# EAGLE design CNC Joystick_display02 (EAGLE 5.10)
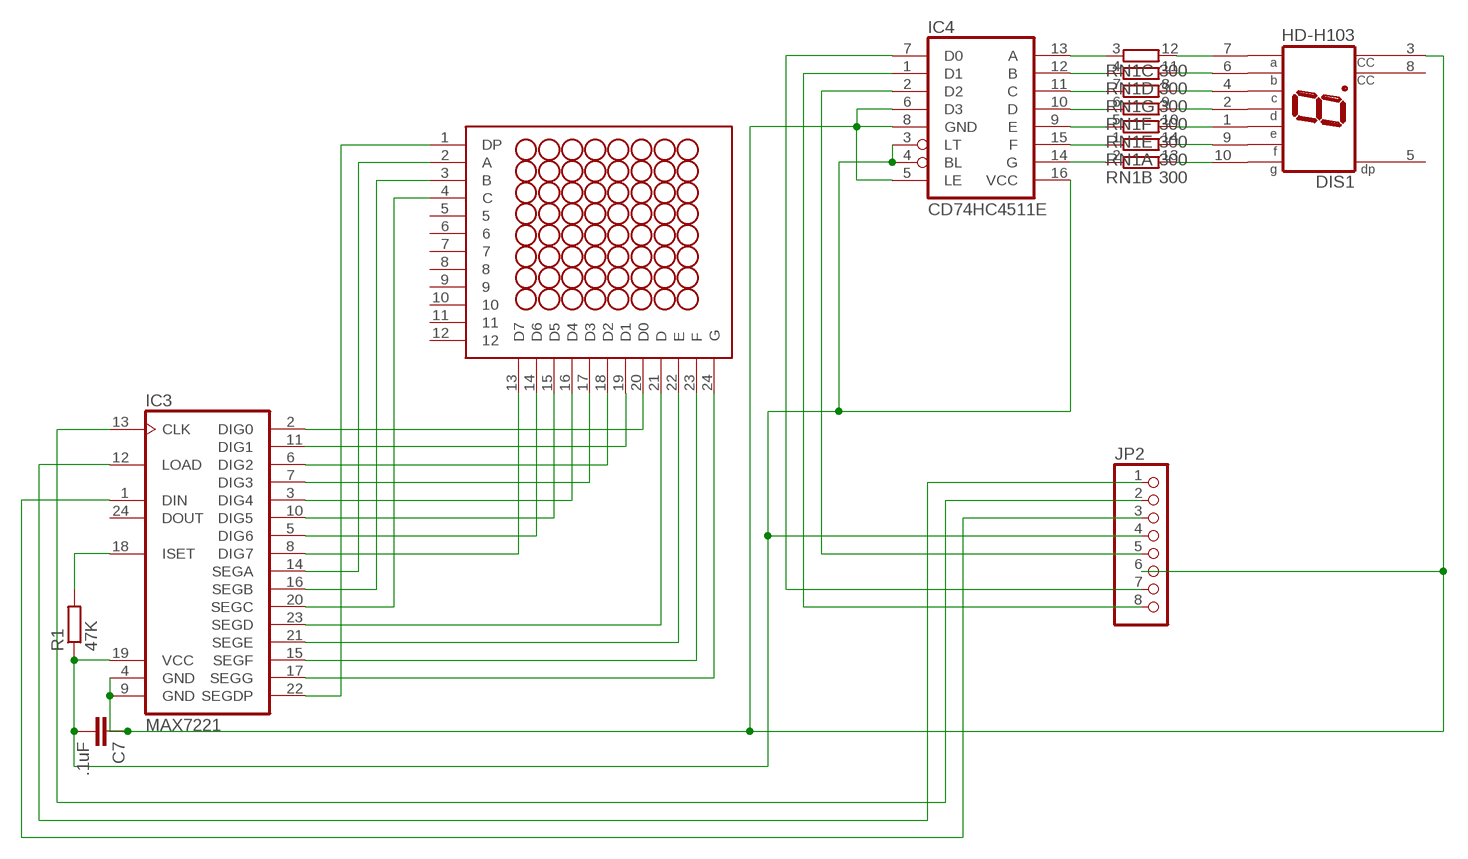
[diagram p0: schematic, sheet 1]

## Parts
C7  .1uF  C-EU050-024X044  [C050-024X044]
DIS1  HD-H103  [HDSP-M]
IC3  MAX7221  MAX7219CNG  [DIL24-3]
IC4  CD74HC4511E  4511N  [DIL16]
JP2  PINHD-1X8/90  [1X08/90]
R1  47K  R-EU_0207/10  [0207/10]
RN1  300  7R-N  [DIL14]
U$1  NFM-12881BG-11  [NFM-12881BG-11]

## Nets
N$1: IC4.13(A) RN1.3
N$2: IC4.12(B) RN1.4
N$3: IC4.9(E) RN1.5
N$4: IC4.10(D) RN1.6
N$5: DIS1.1(E) RN1.10
N$6: IC4.15(F) RN1.1
N$7: IC4.14(G) RN1.2
N$8: DIS1.7(A) RN1.12
N$9: DIS1.6(B) RN1.11
N$10: DIS1.4(C) RN1.8
N$11: DIS1.2(D) RN1.9
N$12: IC4.11(C) RN1.7
N$13: DIS1.9(F) RN1.14
N$14: DIS1.10(G) RN1.13
N$15: IC3.2(DIG0) U$1.20(D0)
N$16: IC3.11(DIG1) U$1.19(D1)
N$17: IC3.6(DIG2) U$1.18(D2)
N$18: IC3.7(DIG3) U$1.17(D3)
N$19: IC3.3(DIG4) U$1.16(D4)
N$20: IC3.10(DIG5) U$1.15(D5)
N$21: IC3.5(DIG6) U$1.14(D6)
N$22: IC3.8(DIG7) U$1.13(D7)
N$23: IC3.23(SEGD) U$1.21(D)
N$24: IC3.21(SEGE) U$1.22(E)
N$25: IC3.15(SEGF) U$1.23(F)
N$26: IC3.17(SEGG) U$1.24(G)
N$27: IC3.14(SEGA) U$1.2(A)
N$28: IC3.16(SEGB) U$1.3(B)
N$29: IC3.20(SEGC) U$1.4(C)
N$30: IC3.22(SEGDP) U$1.1(DP)
N$31: IC4.7(D0) JP2.7
N$33: IC3.13(CLK) JP2.2
N$34: IC4.2(D2) JP2.5
N$38: C7.1 DIS1.3(CC) IC3.4(GND) IC3.9(GND) IC4.5(LE) IC4.6(D3) IC4.8(GND) JP2.6
N$39: IC3.12(LOAD) JP2.1
N$40: IC3.18(ISET) R1.2
N$41: IC4.1(D1) JP2.8
N$44: IC3.1(DIN) JP2.3
N$55: C7.2 IC3.19(VCC) IC4.3(LT) IC4.4(BL) IC4.16(VCC) JP2.4 R1.1
Unconnected: DIS1.5(DP) DIS1.8(CC) IC3.24(DOUT) U$1.5 U$1.6 U$1.7 U$1.8 U$1.9 U$1.10 U$1.11 U$1.12

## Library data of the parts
C7 = rcl:C-EU: CAPACITOR, European symbol
DIS1 = display-hp:HD-H103: LED DISPLAY 1-character 7 segment, decimal point right
IC3 = maxim:MAX7219CNG: LED DISPLAY DRIVER
IC4 = CD74HC4511_BCD:4511: BCD to 7-segment LATCH/DECODER/DRIVER
JP2 = pinhead:PINHD-1X8: PIN HEADER
R1 = rcl:R-EU_: RESISTOR, European symbol
RN1 = resistor-dil:7R-N: DIL RESISTOR
U$1 = edeco:NFM-12881BG-11: 8x8 Red LED Matrix CMX1588ASR

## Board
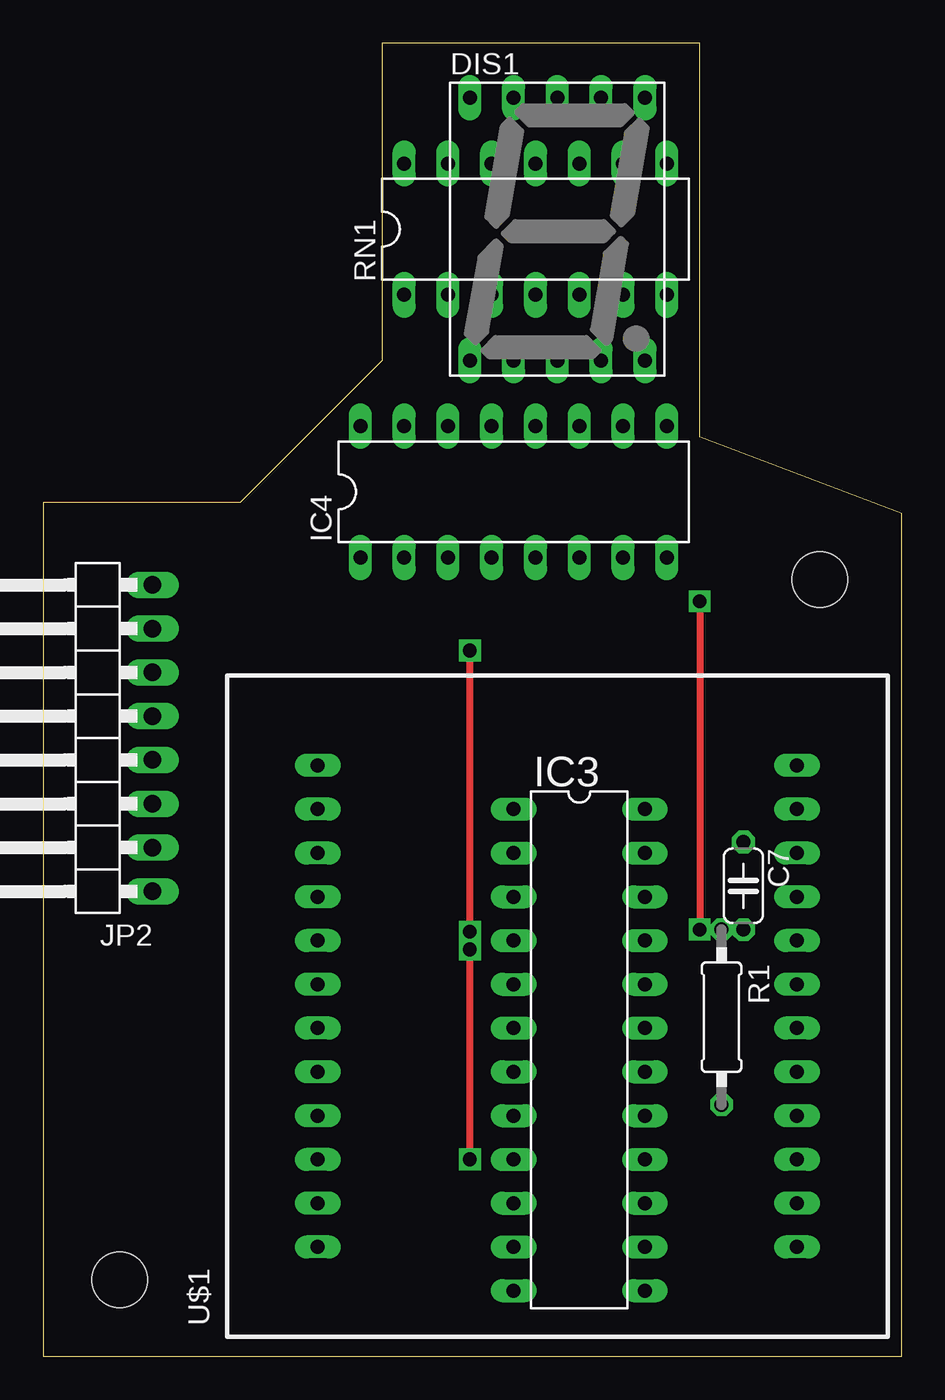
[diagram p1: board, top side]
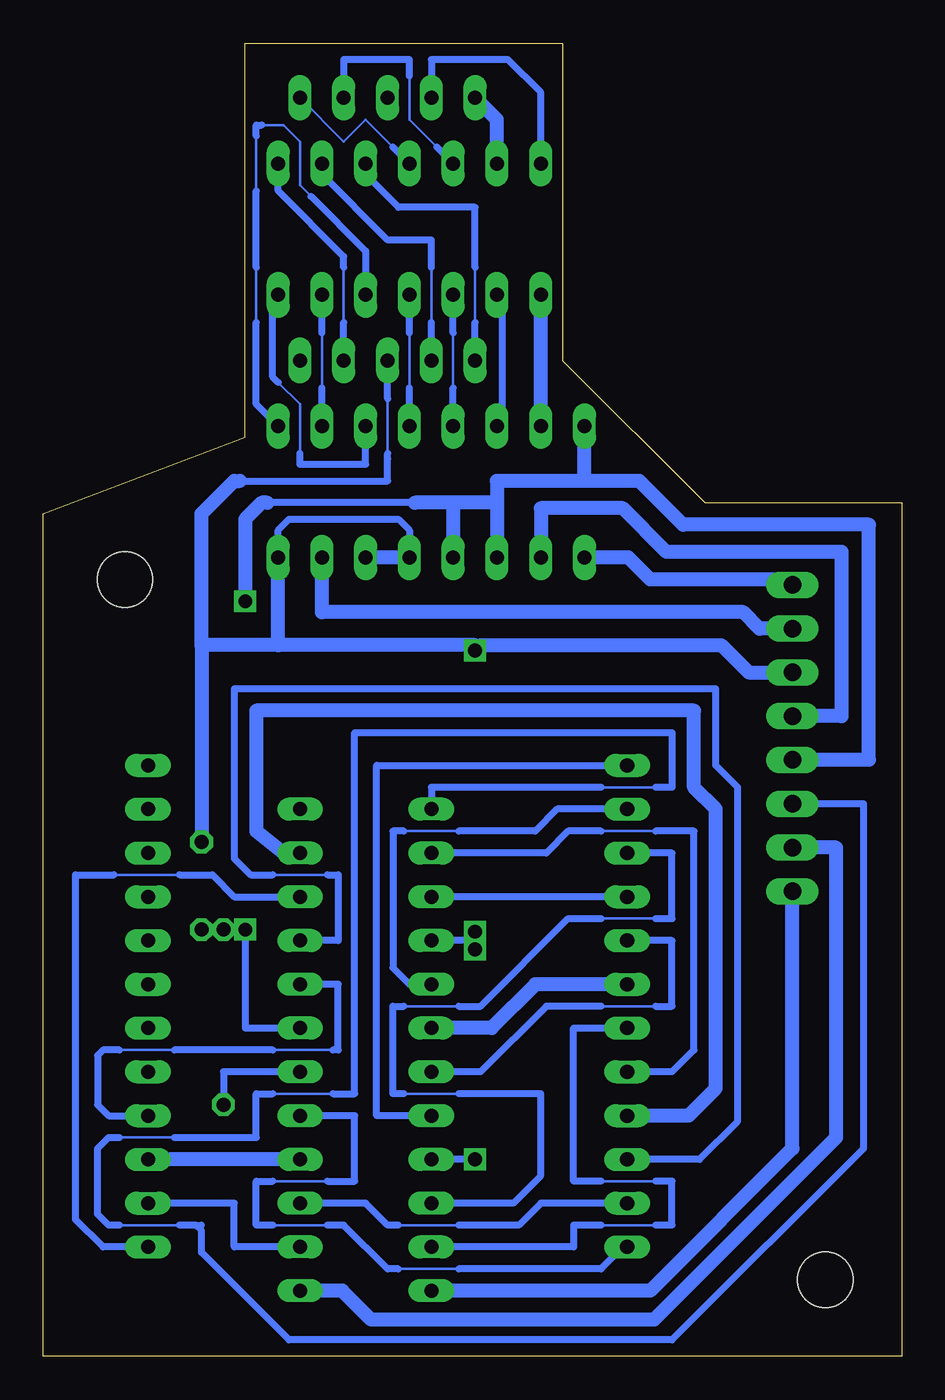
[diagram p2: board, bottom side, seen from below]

Size 49.84 x 76.2 mm. Coordinates in mm from the lower left corner, seen from the top.
Outline: 0,0 49.84,0 49.84,48.9 38.1,53.34 38.1,76.2 19.68,76.2 19.68,57.78 11.43,49.53 0,49.53 0,0
Copper layers (1*16): Top 0.035mm / dielectric 1.5mm / Bottom 0.035mm
Design rules "default": minimum track width 10mil, minimum drill 24mil, track to track 8mil, track to pad 8mil, pad to pad 8mil, via to via 8mil, smd to smd 8mil, copper to edge 40mil, drill to drill 8mil, minimum pad ring 10mil, minimum via ring 8mil, stop-mask expansion 4mil, vias tented up to drill 0mil, thermal gap 10mil
Holes 3.2 mm at 4.45,4.45 45.09,45.09
tRestrict: area 0.5,0.5 to 8.4,8.4; area 41.1,41.1 to 49.1,49.1

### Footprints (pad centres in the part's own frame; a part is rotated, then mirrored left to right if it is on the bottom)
C050-024X044 = drill 0.813 octagon: 1 -2.54,0; 2 2.54,0
HDSP-M = drill 0.813 long: 1 -5.08,-7.62; 2 -2.54,-7.62; 3 0,-7.62; 4 2.54,-7.62; 5 5.08,-7.62; 6 5.08,7.62; 7 2.54,7.62; 8 0,7.62; 9 -2.54,7.62; 10 -5.08,7.62
DIL24-3 = drill 0.813 long: 1 -13.97,-3.81; 2 -11.43,-3.81; 3 -8.89,-3.81; 4 -6.35,-3.81; 5 -3.81,-3.81; 6 -1.27,-3.81; 7 1.27,-3.81; 8 3.81,-3.81; 9 6.35,-3.81; 10 8.89,-3.81; 11 11.43,-3.81; 12 13.97,-3.81; 13 13.97,3.81; 14 11.43,3.81; 15 8.89,3.81; 16 6.35,3.81; 17 3.81,3.81; 18 1.27,3.81; 19 -1.27,3.81; 20 -3.81,3.81; 21 -6.35,3.81; 22 -8.89,3.81; 23 -11.43,3.81; 24 -13.97,3.81
DIL16 = drill 0.813 long: 1 -8.89,-3.81; 2 -6.35,-3.81; 3 -3.81,-3.81; 4 -1.27,-3.81; 5 1.27,-3.81; 6 3.81,-3.81; 7 6.35,-3.81; 8 8.89,-3.81; 9 8.89,3.81; 10 6.35,3.81; 11 3.81,3.81; 12 1.27,3.81; 13 -1.27,3.81; 14 -3.81,3.81; 15 -6.35,3.81; 16 -8.89,3.81
1X08/90 = drill 1.016 long: 1 -8.89,-3.81; 2 -6.35,-3.81; 3 -3.81,-3.81; 4 -1.27,-3.81; 5 1.27,-3.81; 6 3.81,-3.81; 7 6.35,-3.81; 8 8.89,-3.81
0207/10 = drill 0.813 octagon: 1 -5.08,0; 2 5.08,0
DIL14 = drill 0.813 long: 1 -7.62,-3.81; 2 -5.08,-3.81; 3 -2.54,-3.81; 4 0,-3.81; 5 2.54,-3.81; 6 5.08,-3.81; 7 7.62,-3.81; 8 7.62,3.81; 9 5.08,3.81; 10 2.54,3.81; 11 0,3.81; 12 -2.54,3.81; 13 -5.08,3.81; 14 -7.62,3.81
NFM-12881BG-11 = drill 0.813 long: 1 -13.97,-13.905; 2 -11.43,-13.905; 3 -8.89,-13.905; 4 -6.35,-13.905; 5 -3.81,-13.905; 6 -1.27,-13.905; 7 1.27,-13.905; 8 3.81,-13.905; 9 6.35,-13.905; 10 8.89,-13.905; 11 11.43,-13.905; 12 13.97,-13.905; 13 13.97,13.905; 14 11.43,13.905; 15 8.89,13.905; 16 6.35,13.905; 17 3.81,13.905; 18 1.27,13.905; 19 -1.27,13.905; 20 -3.81,13.905; 21 -6.35,13.905; 22 -8.89,13.905; 23 -11.43,13.905; 24 -13.97,13.905

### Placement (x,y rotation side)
C7  40.64,27.3 270 top
DIS1  29.84,65.41 0 top
IC3  31.11,17.78 270 top
IC4  27.3,50.16 0 top
JP2  2.54,35.88 90 top
R1  39.37,19.68 270 top
RN1  28.57,65.41 0 top
U$1  29.84,20.32 90 top

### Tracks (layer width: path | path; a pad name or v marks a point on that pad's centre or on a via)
N$1
  Bottom 0.152: 26.04,56.2 26.04,59.37
  Bottom 0.406: 26.04,59.37 RN1.3 | IC4.13 26.04,56.2
N$2
  Bottom 0.152: 28.57,56.2 28.57,59.37
  Bottom 0.406: 28.57,59.37 RN1.4 | IC4.12 28.57,56.2
N$3
  Bottom 0.152: 37.15,71.44 35.88,71.44 34.92,70.48 34.92,67.94 34.29,67.31 | 37.47,60.01 37.47,63.18 | 37.47,67.63 37.47,70.8
  Bottom 0.406: RN1.5 31.11,64.14 34.29,67.31 | IC4.9 37.47,55.24 37.47,60.01 | 37.15,71.44 37.47,71.44 37.47,70.8 | 37.47,63.18 37.47,67.63
N$4
  Bottom 0.152: 33.66,56.2 33.66,59.37
  Bottom 0.406: 33.66,59.37 RN1.6 | IC4.10 33.66,56.2
N$5
  Bottom 0.152: 24.77,60.01 24.77,63.18
  Bottom 0.406: RN1.10 31.11,68.58 29.21,66.67 24.77,66.67 24.77,63.18 | DIS1.1 24.77,60.01
N$6
  Bottom 0.813: IC4.15 RN1.1
N$7
  Bottom 0.406: IC4.14 23.18,53.98 23.18,61.59 RN1.2
N$8
  Bottom 0.152: 28.57,74.3 28.57,71.75 26.99,70.17
  Bottom 0.406: 28.57,74.3 28.57,75.25 32.38,75.25 DIS1.7 | RN1.12 26.99,70.17
N$9
  Bottom 0.152: DIS1.6 32.38,70.48 31.11,71.75 29.53,70.17
  Bottom 0.406: RN1.11 29.53,70.17
N$10
  Bottom 0.152: 32.38,60.01 32.38,63.18
  Bottom 0.406: DIS1.4 32.38,60.01 | 32.38,63.18 32.38,63.82 36.2,67.63 RN1.8
N$11
  Bottom 0.152: 27.3,60.01 27.3,63.18
  Bottom 0.406: RN1.9 33.66,68.58 29.84,64.77 27.3,64.77 27.3,63.18 | DIS1.2 27.3,60.01
N$12
  Bottom 0.152: 34.92,52.39 34.92,55.24 36.2,56.52
  Bottom 0.406: IC4.11 31.11,51.75 34.92,51.75 34.92,52.39 | RN1.7 36.51,61.28 36.51,56.83 36.2,56.52
N$13
  Bottom 0.406: RN1.14 20.95,73.34 22.86,75.25 27.3,75.25 DIS1.9
N$14
  Bottom 0.813: RN1.13 23.5,71.75 DIS1.10
N$15
  Bottom 0.152: 14.29,30.48 17.46,30.48
  Bottom 0.406: IC3.2 20.64,29.21 19.37,30.48 17.46,30.48 | 14.29,30.48 12.06,30.48 12.06,17.78 13.34,16.51 U$1.20
N$16
  Bottom 0.152: 14.29,7.62 17.46,7.62 | 14.29,10.16 17.46,10.16
  Bottom 0.406: IC3.11 19.05,6.35 19.05,7.62 17.46,7.62 | 17.46,10.16 19.05,10.16 19.05,19.05 U$1.19 | 14.29,7.62 13.34,7.62 13.34,10.16 14.29,10.16
N$17
  Bottom 0.813: IC3.6 23.81,19.05 21.27,21.59 U$1.18
N$18
  Bottom 0.152: 14.29,20.32 17.46,20.32
  Bottom 0.406: IC3.7 24.45,16.51 20.64,20.32 17.46,20.32 | 14.29,20.32 13.34,20.32 13.34,24.13 U$1.17
N$19
  Bottom 0.406: U$1.16 IC3.3
N$20
  Bottom 0.152: 17.46,25.4 14.29,25.4 | 28.89,20.32 25.72,20.32 | 25.72,15.24 28.89,15.24
  Bottom 0.406: IC3.10 22.54,8.89 20.95,10.48 20.95,15.24 25.72,15.24 | 14.29,25.4 13.34,25.4 13.34,29.21 U$1.15 | 17.46,25.4 19.37,25.4 24.45,20.32 25.72,20.32 | 28.89,20.32 29.53,20.32 29.53,15.24 28.89,15.24
N$21
  Bottom 0.152: 25.72,30.48 28.89,30.48
  Bottom 0.406: IC3.5 28.57,21.59 29.53,22.54 29.53,30.48 28.89,30.48 | 25.72,30.48 21.27,30.48 20,31.75 U$1.14
N$22
  Bottom 0.406: IC3.8 30.48,13.97 30.48,34.29 U$1.13
N$23
  Bottom 0.813: IC3.23 35.88,29.21 37.47,30.48 37.47,37.47 12.06,37.47 12.06,33.02 10.79,31.75 10.79,15.56 12.38,13.97 U$1.21
N$24
  Bottom 0.152: 36.51,27.94 33.34,27.94
  Bottom 0.406: 36.51,27.94 37.78,27.94 38.73,28.89 38.73,38.73 10.79,38.73 10.79,34.29 9.53,33.02 9.53,13.65 11.75,11.43 U$1.22 | IC3.21 32.7,24.13 32.7,27.94 33.34,27.94
N$25
  Bottom 0.152: 25.72,7.62 29.21,7.62
  Bottom 0.406: IC3.15 31.11,8.89 29.84,7.62 29.21,7.62 | 25.72,7.62 22.23,7.62 20.95,8.89 U$1.23
N$26
  Bottom 0.152: 25.72,5.08 29.21,5.08 | 36.51,10.16 33.34,10.16 | 33.34,7.62 36.51,7.62
  Bottom 0.406: IC3.17 31.75,13.97 31.75,10.16 33.34,10.16 | 33.34,7.62 32.38,7.62 29.84,5.08 29.21,5.08 | 25.72,5.08 17.46,5.08 16.19,6.35 U$1.24 | 36.51,10.16 37.47,10.16 37.47,7.62 36.51,7.62
N$27
  Bottom 0.406: IC3.14 38.73,6.35 38.73,8.89 U$1.2
N$28
  Bottom 0.813: IC3.16 U$1.3
N$29
  Bottom 0.152: 33.02,17.78 36.51,17.78 | 42.23,17.78 45.4,17.78
  Bottom 0.406: U$1.4 46.04,13.97 46.67,14.61 46.67,17.46 46.35,17.78 45.4,17.78 | IC3.20 32.7,21.59 32.7,17.78 33.02,17.78 | 36.51,17.78 42.23,17.78
N$30
  Bottom 0.152: 45.72,27.94 41.91,27.94
  Bottom 0.406: IC3.22 38.73,26.67 40.01,27.94 41.91,27.94 | 45.72,27.94 47.94,27.94 47.94,7.94 46.35,6.35 U$1.1
N$31
  Bottom 0.813: IC4.7 33.66,43.18 9.21,43.18 8.26,42.23 JP2.7
N$33
  Bottom 0.813: JP2.2 3.81,29.53 3.81,12.7 14.38,2.13 30.8,2.13 32.48,3.81 IC3.13
N$34
  Bottom 0.813: IC4.2 20.95,49.21 16.19,49.21 13.65,46.67 3.49,46.67 3.49,37.15 JP2.5
N$38  (via drill 0.8 pad 1.27)
  Top 0.406: v24.77,24.64 v24.77,40.96 | v24.77,11.43 v24.77,23.62
  Bottom 0.152: 29.84,52.07 29.84,55.56
  Bottom 0.406: IC4.5 28.57,47.94 29.21,48.58 35.56,48.58 36.2,47.94 IC4.8 | v24.77,11.43 IC3.9 | 24.77,24.13 v24.77,24.64 | v24.77,23.62 24.77,24.13 | 24.77,24.13 IC3.4 | v24.77,40.96 24.77,41.27 | 29.84,52.39 29.84,52.07 29.84,50.8 38.42,50.8 | 29.84,55.56 DIS1.3
  Bottom 0.813: 36.2,41.27 IC4.8 | 40.64,41.27 40.64,48.9 38.73,50.8 38.42,50.8 | 36.2,41.27 40.64,41.27 | 24.77,41.27 36.2,41.27 | 40.64,41.27 C7.1 | JP2.6 8.89,39.69 10.48,41.27 24.45,41.27 v24.77,40.96 | IC4.5 IC4.6
N$39
  Bottom 0.813: IC3.12 14.61,3.81 6.35,12.06 JP2.1
N$40
  Bottom 0.406: IC3.18 39.37,16.51 R1.2
N$41
  Bottom 0.813: JP2.8 6.67,45.09 14.61,45.09 15.88,46.35 IC4.1
N$44
  Bottom 0.152: 36.51,15.24 33.02,15.24 | 14.29,33.02 17.46,33.02 | 45.4,12.7 42.23,12.7 | 41.91,7.62 45.4,7.62
  Bottom 0.406: IC3.1 27.3,33.02 17.46,33.02 | 40.96,7.62 41.91,7.62 | 40.96,7.62 40.64,7.62 | 42.23,12.7 37.47,12.7 37.47,15.24 36.51,15.24 | 33.02,15.24 31.75,15.24 31.75,36.2 13.34,36.2 13.34,33.02 14.29,33.02 | JP2.3 2.22,32.07 2.22,12.06 13.34,0.95 35.56,0.95 40.64,6.03 40.64,7.3 40.96,7.62 | 45.4,12.7 46.04,12.7 46.67,12.06 46.67,8.26 46.04,7.62 45.4,7.62
N$55  (via drill 0.8 pad 1.27)
  Top 0.406: v38.1,43.81 v38.1,24.77
  Bottom 0.406: IC3.19 38.1,19.05 v38.1,24.77 R1.1 C7.2 | 28.26,49.53 36.83,49.53
  Bottom 0.813: 18.41,50.8 23.5,50.8 23.5,49.53 | 18.41,50.8 IC4.16 | 18.41,50.8 15.24,50.8 12.7,48.26 1.91,48.26 1.91,34.61 JP2.4 | v38.1,43.81 38.1,48.58 37.15,49.53 36.83,49.53 | 23.5,49.53 IC4.3 | 23.5,49.53 26.04,49.53 | 26.04,49.53 28.26,49.53 | 26.04,49.53 IC4.4

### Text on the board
Document: D1 | D0 | GND | D2 | 5V | Din | Clk | Load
